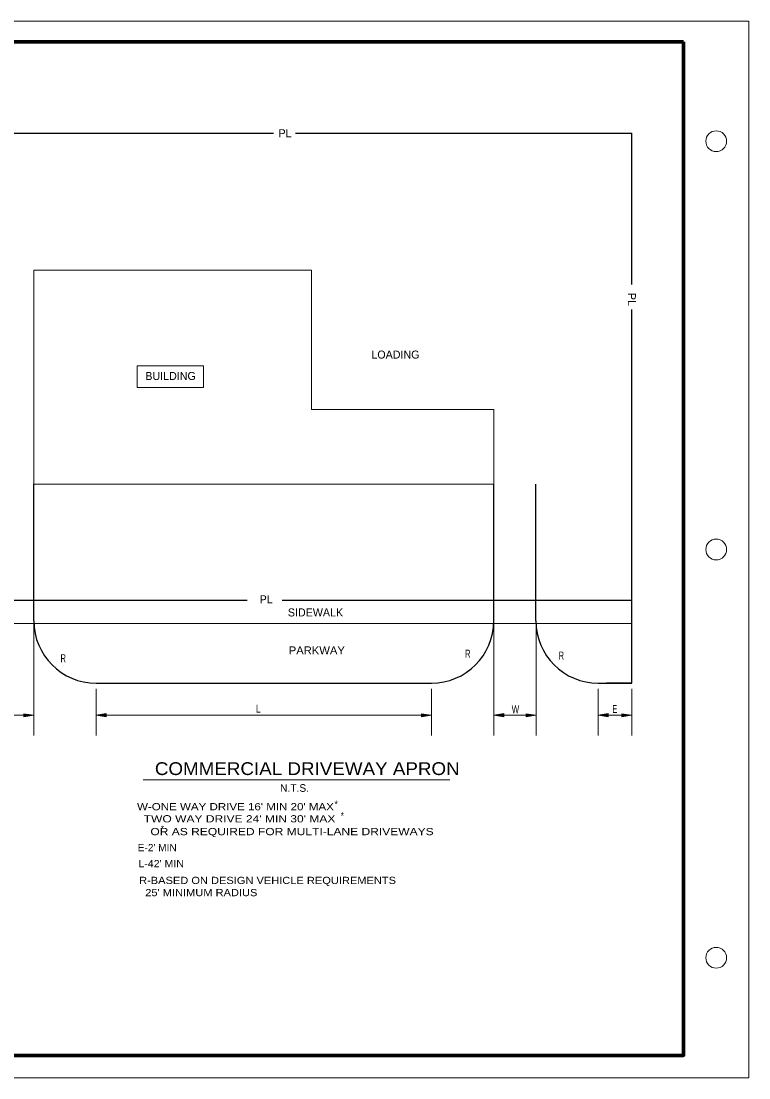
# Model space of a CAD drawing. Extents: x 124.7 to 141.7, y -6.7 to 4.3.
# Drawn here: x 134.08 to 141.67, y -6.71 to 4.3 of the extents above; entities that cross this region are included whole.
import ezdxf

# ---------------------------------------------------------------- set-up
doc = ezdxf.new("R2010")
doc.units = 0
doc.header["$LTSCALE"] = 0.033
for name, color, linetype, lineweight in [('1', 7, 'Continuous', 13), ('6', 7, 'Continuous', 13), ('60', 7, 'Continuous', 13), ('7', 7, 'Continuous', 13), ('8', 7, 'Continuous', 13)]:
    doc.layers.add(name, color=color, linetype=linetype, lineweight=lineweight)

msp = doc.modelspace()

# ---------------------------------------------------------------- linework, layer by layer
at = {"layer": '1'}
for p, q in [((134.21451, -0.52552), (134.21451, 1.70292)), ((137.10919, 1.70292), (134.21451, 1.70292)), ((132.77677, -1.97616), (140.44549, -1.97616)), ((134.21513, -1.97616), (134.21513, -3.14385)), ((139.00715, -1.97616), (139.00715, -3.14385)), ((139.44837, -1.97616), (139.44837, -3.14385)), ((134.86451, -2.6579), (134.86451, -3.14385)), ((138.35773, -2.6579), (138.35773, -3.14385)), ((140.09773, -2.6579), (140.09773, -3.14385)), ((140.44549, -2.6579), (140.44549, -3.14385)), ((133.7739, -2.93135), (134.21513, -2.93135)), ((134.86451, -2.93135), (138.35773, -2.93135)), ((139.00715, -2.93135), (139.44837, -2.93135)), ((139.00715, -2.93135), (139.44837, -2.93135)), ((140.09773, -2.93135), (140.44549, -2.93135)), ((140.09773, -2.93135), (140.44546, -2.93135))]:
    msp.add_line(p, q, dxfattribs=at)
msp.add_lwpolyline([(134.21451, -0.52552), (139.00783, -0.52545), (139.00783, 0.25417), (137.10919, 0.25417), (137.10919, 1.70292)], dxfattribs=at)
msp.add_lwpolyline([(135.29042, 0.70871), (135.98433, 0.70871), (135.98433, 0.48081), (135.29042, 0.48081)], close=True, dxfattribs=at)
at = {"layer": '6', "lineweight": 25}
for p, q in [((132.77677, 3.13027), (136.71186, 3.13027)), ((136.94218, 3.13027), (140.44549, 3.13027)), ((140.44549, 1.55611), (140.44549, 3.13027)), ((140.44549, -2.5979), (140.44549, 1.29376)), ((134.21451, -1.9479), (134.21451, -0.52552)), ((139.00776, -1.94782), (139.00783, -0.52545)), ((139.44776, -1.94784), (139.44783, -0.52548)), ((132.77677, -1.73298), (136.43812, -1.73298)), ((136.80193, -1.73298), (140.44549, -1.73298)), ((134.86451, -2.5979), (138.35773, -2.59779)), ((140.09773, -2.59787), (140.44549, -2.5979)), ((140.44548, -2.5979), (140.18293, -2.5979))]:
    msp.add_line(p, q, dxfattribs=at)
for centre, start, end in [((134.86451, -1.94789), 180, 270), ((138.35776, -1.94779), 269.99724, 359.99724), ((140.09776, -1.94787), 179.99724, 269.99724)]:
    msp.add_arc(centre, 0.65, start, end, dxfattribs=at)
at = {"layer": '60'}
msp.add_lwpolyline([(141.66697, -6.70846), (124.65648, -6.70846), (124.65648, 4.29833), (141.66697, 4.29833)], close=True, dxfattribs=at)
at = {"layer": '60', "lineweight": 70}
msp.add_lwpolyline([(140.98583, 4.08146), (124.91782, 4.08146), (124.91782, -6.47409), (140.98583, -6.47409)], close=True, dxfattribs=at)
at = {"layer": '60'}
for centre in [(141.3264, 3.04757), (141.3264, -1.20505), (141.3264, -5.45767)]:
    msp.add_circle(centre, 0.10834, dxfattribs=at)
at = {"layer": '7'}
msp.add_line((135.35459, -3.60416), (138.5491, -3.60416), dxfattribs=at)
at = {"layer": '8'}
for points in [[(134.2146, -2.93068), (134.11087, -2.91578), (134.11087, -2.94802), (134.21497, -2.93104)], [(134.11096, -2.92094), (134.21513, -2.93135), (134.11096, -2.93135), (134.11096, -2.93656), (134.21513, -2.93135), (134.11096, -2.94177), (134.11096, -2.92615), (134.20992, -2.93135)], [(134.96868, -2.94177), (134.86451, -2.93135), (134.96868, -2.93135), (134.96868, -2.92615), (134.86451, -2.93135), (134.96868, -2.92094), (134.96868, -2.93656), (134.86972, -2.93135)], [(134.86503, -2.93203), (134.96875, -2.94693), (134.96875, -2.91469), (134.86467, -2.93167)], [(138.35721, -2.93068), (138.25348, -2.91578), (138.25348, -2.94802), (138.35757, -2.93104)], [(138.25356, -2.92094), (138.35773, -2.93135), (138.25356, -2.93135), (138.25356, -2.93656), (138.35773, -2.93135), (138.25356, -2.94177), (138.25356, -2.92615), (138.35252, -2.93135)], [(139.11131, -2.94177), (139.00715, -2.93135), (139.11131, -2.93135), (139.11131, -2.92615), (139.00715, -2.93135), (139.11131, -2.92094), (139.11131, -2.93656), (139.01235, -2.93135)], [(139.00767, -2.93203), (139.11139, -2.94693), (139.11139, -2.91469), (139.0073, -2.93167)], [(139.44785, -2.93068), (139.34412, -2.91578), (139.34412, -2.94802), (139.44822, -2.93104)], [(139.34421, -2.92094), (139.44837, -2.93135), (139.34421, -2.93135), (139.34421, -2.93656), (139.44837, -2.93135), (139.34421, -2.94177), (139.34421, -2.92615), (139.44317, -2.93135)], [(140.2019, -2.94177), (140.09773, -2.93135), (140.2019, -2.93135), (140.2019, -2.92615), (140.09773, -2.93135), (140.2019, -2.92094), (140.2019, -2.93656), (140.10294, -2.93135)], [(140.09825, -2.93203), (140.20197, -2.94693), (140.20197, -2.91469), (140.09789, -2.93167)], [(140.44494, -2.93068), (140.34122, -2.91578), (140.34122, -2.94802), (140.4453, -2.93104)], [(140.34129, -2.92094), (140.44546, -2.93135), (140.34129, -2.93135), (140.34129, -2.93656), (140.44546, -2.93135), (140.34129, -2.94177), (140.34129, -2.92615), (140.44025, -2.93135)]]:
    msp.add_lwpolyline(points, dxfattribs=at)

# ---------------------------------------------------------------- texts
at = {"layer": '1'}
for s, width, p in [("W-ONE WAY DRIVE 16' MIN 20' MAX", 1.2, (135.29026, -3.92127)), ('*', 0.85, (137.34862, -3.89437)), ('*', 0.85, (137.41302, -4.01604)), ("  TWO WAY DRIVE 24' MIN 30' MAX", 1.25, (135.29026, -4.04748)), ('    OR AS REQUIRED FOR MULTI-LANE DRIVEWAYS', 1.25, (135.29026, -4.18083)), ('*', 0.85, (135.53859, -4.15202)), ("E-2' MIN", 1.05, (135.29741, -4.34744)), ("L-42' MIN", 1.1, (135.30456, -4.51404)), ('R-BASED ON DESIGN VEHICLE REQUIREMENTS', 1.15, (135.31172, -4.68912)), ("  25' MINIMUM RADIUS", 1.15, (135.31172, -4.81618))]:
    msp.add_text(s, height=0.07497, dxfattribs=dict(at, width=width)).set_placement(p)
at = {"layer": '6'}
for s, height, p in [('PL', 0.08333, (136.76445, 3.08972)), ('LOADING', 0.08333, (137.73257, 0.78352)), ('BUILDING', 0.08333, (135.3766, 0.56064)), ('PL', 0.08333, (136.56805, -1.76528)), ('SIDEWALK', 0.08333, (136.86225, -1.90222)), ('N.T.S.', 0.07964, (136.78094, -3.729))]:
    msp.add_text(s, height=height, dxfattribs=at).set_placement(p)
msp.add_text('PL', height=0.08333, rotation=270, dxfattribs=at).set_placement((140.4058, 1.46778))
for s, width, p in [('R', 0.7, (134.49305, -2.3798)), ('PARKWAY', 1.05, (136.87132, -2.2976)), ('R', 0.7, (138.70977, -2.33231)), ('R', 0.7, (139.68416, -2.3513)), ('L', 0.75, (136.53043, -2.90373)), ('W', 0.75, (139.1949, -2.91046)), ('E', 0.7, (140.24354, -2.90775))]:
    msp.add_text(s, height=0.08333, dxfattribs=dict(at, width=width)).set_placement(p)
at = {"layer": '7', "width": 1.1}
msp.add_text('COMMERCIAL DRIVEWAY APRON', height=0.1331, dxfattribs=at).set_placement((135.47609, -3.55416))

doc.saveas('drawing.dxf')
